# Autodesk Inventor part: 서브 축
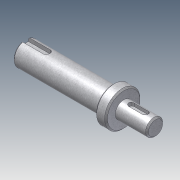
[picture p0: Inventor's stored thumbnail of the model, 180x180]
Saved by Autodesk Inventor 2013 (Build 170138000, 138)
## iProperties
Company: 한국ATC센터
Created: 2014-10
Part Number: 서브 축
Document SubType Name: Modeling
Designer: KYOUNG IL JANG
Density: 1 g/cm^3
Mass: 19.9624 g
Surface Area: 57.7178 cm^2
Volume: 19.9624 cm^3
Material: 일반
Author: KYOUNG IL JANG
Revision Number: 1
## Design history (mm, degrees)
sketch "스케치1"
  geometry: L1 (-16.331, 0)-(-108.831, 0); L2 (-16.331, 0)-(-16.331, -6); L3 (-16.331, -6)-(-38.831, -6); L4 (-38.831, -12.5)-(-46.5, -12.5); L5 (-46.5, -8.5)-(-108.831, -8.5); L6 (-108.831, -8.5)-(-108.831, 0); L7 (-46.5, -8.5)-(-46.5, -12.5); L8 (-38.831, -6)-(-38.831, -12.5); L9 (-46.5, 12.249)-(-46.5, -12.249) reference; L10 (-38.831, -17)-(-38.831, 17) reference; 2 further points
  constraints: 17 end point, 4 perpendicular, 2 collinear, 2 parallel, 1 horizontal, 1 midpoint, 1 point on line
  dimensions: "d1" = 12 diameter of L3 L1; "d2" = 25 diameter of L4 L1; "d3" = 17 diameter of L5 L1; "d4" = 62.33128 distance of L5.start L5.end (derived); "d18" = 22.5 distance of L2.end L3.end; "d20" = 70 distance between parallel lines of L6 L8
revolve "회전1" sketch "스케치1" stored, may be unused: angle "d5" = 90 deg
chamfer "모따기1" distance "d6" = 1; stored, may be unused: second distance "d7" = 2, angle "d8" = 45 deg
node "작업 평면1"
sketch "스케치2"
  geometry: L1 (11.25, 5)-(11.25, -5) reference; L2 (-5.75, -2)-(4.25, -2); L3 (4.25, 2)-(-5.75, 2); A1 r 2 centre (4.25, 0) between (4.25, -2) and (4.25, 2); A2 r 2 centre (-5.75, 0) between (-5.75, 2) and (-5.75, -2); 2 further points
  constraints: 4 end point, 4 point on circle, 4 tangent, 2 centre point, 1 horizontal alignment, 1 midpoint, 1 parallel, 1 perpendicular
  dimensions: "d9" = 4 distance between parallel lines of L2 L3; "d10" = 14 dimension on A1 A2; "d11" = 5 distance edge to line of A1 L1
extrude "돌출1" cut sketch "스케치2" distance "d12" = 2.5; taper "d13" = 0 deg
node "작업 평면2"
sketch "스케치3"
  geometry: L1 (-31.166, -7.5)-(-31.166, 7.5) reference; L2 (-31.166, 2.5)-(-15.666, 2.5); L3 (-15.666, -2.5)-(-31.166, -2.5); A1 r 2.5 centre (-15.666, 0) between (-15.666, -2.5) and (-15.666, 2.5); 2 further points
  constraints: 4 end point, 2 perpendicular, 2 point on circle, 2 point on line, 2 tangent, 1 centre point, 1 horizontal alignment, 1 midpoint
  dimensions: "d14" = 5 distance between parallel lines of L3 L2; "d15" = 18 dimension on A1 L1
extrude "돌출2" cut sketch "스케치3" distance "d16" = 3; taper "d17" = 0 deg
node "솔리드1"
node "참조4"
node "참조5"
